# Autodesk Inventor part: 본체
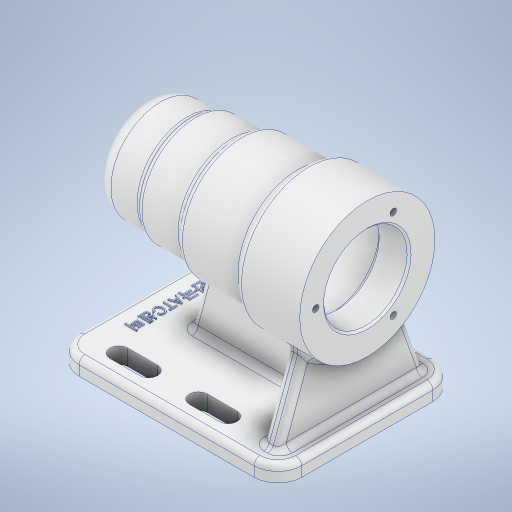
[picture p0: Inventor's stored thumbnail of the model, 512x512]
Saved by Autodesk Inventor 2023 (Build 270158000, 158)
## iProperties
Created: 2022-07
Part Number: 본체
Material: 알루미늄 6061
Document SubType Name: Modeling
Designer: owner
Density: 2.7 g/cm^3
Appearance: 알루미늄 - 평지
Mass: 693.1 g
Surface Area: 698.776 cm^2
Volume: 256.704 cm^3
Author: owner
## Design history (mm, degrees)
sketch "스케치1"
  geometry: L1 (44, -45)-(-44, -45); L2 (-56, -33)-(-56, 33); L3 (-44, 45)-(44, 45); L4 (56, 33)-(56, -33); L5 (56, -45)-(-56, 45); L6 (-56, -45)-(56, 45); A1 r 12 centre (44, 33) between (56, 33) and (44, 45); A2 r 12 centre (44, -33) between (44, -45) and (56, -33); A3 r 12 centre (-44, -33) between (-56, -33) and (-44, -45); A4 r 12 centre (-44, 33) between (-44, 45) and (-56, 33); 1 further point
  constraints: 12 end point, 8 point on circle, 8 point on line, 8 tangent, 4 centre point, 3 equal radius, 2 midpoint, 2 parallel, 1 horizontal, 1 perpendicular
  dimensions: "d0" = 112 distance between parallel lines of L2 L4; "d1" = 90 distance of L6.start L5.end; "d4" = 12 radius of A1
extrude "돌출1" new body sketch "스케치1" distance "d2" = 8; taper "d3" = 0 deg
sketch "스케치2"
  geometry: L1 (-36, -33)-(-21, -33); L2 (-36, -37.5)-(-21, -37.5); L3 (-21, -28.5)-(-36, -28.5); L4 (-56, 33)-(-56, -33) reference; L5 (-44, -45)-(44, -45) reference; L6 (19, -28.5)-(4, -28.5); L7 (4, -37.5)-(19, -37.5); L8 (-21, 37.5)-(-36, 37.5); L9 (-36, 28.5)-(-21, 28.5); L10 (19, 37.5)-(4, 37.5); L11 (4, 28.5)-(19, 28.5); A1 r 4.5 centre (-36, -33) between (-36, -28.5) and (-36, -37.5); A2 r 4.5 centre (-21, -33) between (-21, -37.5) and (-21, -28.5); A3 r 4.5 centre (19, -33) between (19, -37.5) and (19, -28.5); A4 r 4.5 centre (4, -33) between (4, -28.5) and (4, -37.5); A5 r 4.5 centre (-21, 33) between (-21, 28.5) and (-21, 37.5); A6 r 4.5 centre (-36, 33) between (-36, 37.5) and (-36, 28.5); A7 r 4.5 centre (19, 33) between (19, 28.5) and (19, 37.5); A8 r 4.5 centre (4, 33) between (4, 37.5) and (4, 28.5); 2 further points
  constraints: 20 end point, 16 point on circle, 8 centre point, 4 tangent, 2 horizontal, 1 midpoint, 1 parallel, 1 vertical, 30 other
  dimensions: "d5" = 15 distance of L1.start L1.end; "d6" = 9 diameter of A2; "d7" = 20 distance from line of L1.start L4; "d8" = 33 distance from line of L1 point (0, 0); "d11" = 40 distance of L1.end A3.centre; "d14" = 66 distance of L1.end A5.centre
extrude "돌출2" cut sketch "스케치2" stored distance "d17" = 8; taper "d18" = 0 deg
fillet "모깎기1" dims "d19" = 3
sketch "스케치3"
  geometry: L1 (-56, 33)-(-56, -33) reference; 2 further points
  constraints: 1 horizontal alignment, 1 other
  dimensions: "d20" = 12 distance from line of point (-44, 0) L1
feature "엠보싱1" sketch "스케치3" dims "d0" = 112, "d1" = 90, "d2" = 8, "d4" = 12, "d21" = 0.5, "d22" = 0
sketch "스케치4"
  geometry: L1 (-56, 70)-(56, 70); L2 (-44, 0)-(44, 0) reference; L3 (-47, 80.5)-(-47, 85.7); L4 (-46.7, 86)-(-43, 86); L5 (-43, 86)-(-43, 87.2); L6 (-42.7, 87.5)-(-25, 87.5); L7 (-25, 87.5)-(-25, 90.7); L8 (-24.7, 91)-(-13, 91); L9 (-13, 91)-(-13, 91); L10 (-10, 94)-(38, 94); L11 (41, 91)-(41, 91); L12 (41, 91)-(55, 91); L13 (56, 104)-(56, 92); L14 (-56, 87)-(-56, 70); L15 (-48, 95)-(-32, 95); L16 (-32, 95)-(-32, 97); L17 (-32, 97)-(-10, 97); L18 (-10, 97)-(-10, 100); L19 (-10, 100)-(24, 100); L20 (24, 100)-(24, 104); L21 (24, 104)-(56, 104); L22 (-47, 80.5)-(-47, 80.5); L23 (-50, 77.5)-(-50, 70); L24 (56, 0)-(56, 5) reference; L25 (55, 91)-(56, 92); A1 r 8 centre (-48, 87) between (-48, 95) and (-56, 87); A2 r 3 centre (-47, 77.5) between (-47, 80.5) and (-50, 77.5); A3 r 3 centre (-10, 91) between (-10, 94) and (-13, 91); A4 r 3 centre (38, 91) between (41, 91) and (38, 94); A5 r 0.3 centre (-46.7, 85.7) between (-46.7, 86) and (-47, 85.7); A6 r 0.3 centre (-42.7, 87.2) between (-42.7, 87.5) and (-43, 87.2); A7 r 0.3 centre (-24.7, 90.7) between (-24.7, 91) and (-25, 90.7); 7 further points
  constraints: 46 end point, 17 perpendicular, 14 point on circle, 14 tangent, 8 point on line, 7 centre point, 4 equal radius, 3 horizontal, 2 collinear, 1 vertical
  dimensions: "d23" = 70 distance between parallel lines of L1 L2; "d24" = 112 distance between parallel lines of L13 L14; "d28" = 42 diameter of L8 L1; "d29" = 48 diameter of L10 L1; "d36" = 4 distance between parallel lines of L5 L3; "d37" = 18 distance between parallel lines of L7 L5; "d38" = 12 distance between parallel lines of L9 L7; "d39" = 54 distance between parallel lines of L11 L9; "d40" = 3 distance of L3.start point (-50, 80.5); "d41" = 15 distance between parallel lines of L13 L11; "d42" = 21 diameter of L22 L1; "d43" = 32 diameter of L4 L1; "d44" = 35 diameter of L6 L1; "d45" = 50 diameter of L15 L1; "d46" = 54 diameter of L17 L1; "d47" = 60 diameter of L19 L1; "d48" = 24 distance between parallel lines of L14 L16; "d49" = 46 distance between parallel lines of L18 L14; "d50" = 80 distance between parallel lines of L14 L20; "d51" = 68 diameter of L21 L1; "d52" = 8 radius of A1; "d53" = 3 radius of A2; "d54" = 1 distance of L12.end point (56, 91); "d55" = 1 distance of L13.end point (56, 91) (= d54); "d56" = 0.3 radius of A5
revolve "회전1" sketch "스케치4" stored, may be unused: angle "d57" = 90 deg
fillet "모깎기2" dims "d58" = 3
sketch "스케치5" dims "d59" = 52
  geometry: C1 r 15.7 at (0, 0) reference; C2 r 2 at (-26, 0); 2 further points
  constraints: 2 horizontal alignment, 1 centre point, 1 coincident, 2 other
  dimensions: "d60" = 4 diameter of C2
hole "구멍1" sketch "스케치5" at (-26, 0) diameter "d61" = 3.242; stored, may be unused: countersink angle "d65" = 90 deg, drill point angle "d67" = 118 deg; dims "d62" = 8, "d63" = 4, "d64" = 2, "d66" = 11
node "작업 평면1"
sketch "스케치6"
  geometry: L1 (9.591, 45.342)-(-4, 8); L2 (56.409, 45.342)-(70, 8); L3 (-12, 0)-(-12, 5) reference; L4 (0, 8)-(66, 8) reference; L5 (-9, 8)-(0, 8) reference; L6 (66, 8)-(75, 8) reference; L7 (78, 0)-(78, 5) reference; A1 r 34 centre (33, 70) between (9.591, 45.342) and (56.409, 45.342) reference; 1 further point
  constraints: 4 end point, 2 point on circle, 2 point on line
  dimensions: "d72" = 8 distance from line of L1.end L3; "d73" = 110 deg angle of L1 L5; "d74" = 110 deg angle of L2 L6; "d75" = 8 distance from line of L2.end L7
extrude "돌출3" join sketch "스케치6" distance "d76" = 8; taper "d77" = 0 deg
sketch "스케치7"
  geometry: L1 (-19.622, 43)-(-29, 8); L2 (48, 8)-(48, 45.342) reference; L3 (-30.356, 43)-(-12.196, 43) reference; L4 (-7, 40)-(21, 40) reference; L5 (26.657, 36)-(56, 36) reference; L6 (40, 45.342)-(40, 8) reference; L7 (-44, 8)-(44, 8) reference; A1 r 3 centre (-12.196, 40) between (-9.598, 41.5) and (-12.196, 43) reference; A2 r 3 centre (-7, 43) between (-9.598, 41.5) and (-7, 40) reference; A3 r 3 centre (21, 37) between (23.828, 38) and (21, 40) reference; A4 r 3 centre (26.657, 39) between (23.828, 38) and (26.657, 36) reference; 1 further point
  constraints: 2 end point, 2 point on line
  dimensions: "d78" = 77 distance from line of L2 L1.end; "d80" = 105 deg angle of L1 L7
feature "리브1" sketch "스케치7" dims "d81" = 1, "d82" = 8, "d83" = 0, "d84" = 0, "d85" = 1, "d86" = 1
fillet "모깎기3" dims "d87" = 3
fillet "모깎기4" dims "d88" = 3
node "솔리드1"
pattern_circular "원형 패턴1" dims angle "d69" = 360 deg
feature "A9D066F2-1C7D-4E18-AEED-F7BC21143FA4" dims "d61" = 3.242, "d62" = 8, "d63" = 4, "d64" = 2, "d65" = 90 deg, "d66" = 11, "d67" = 118 deg
other parameters: "d71" = -8
